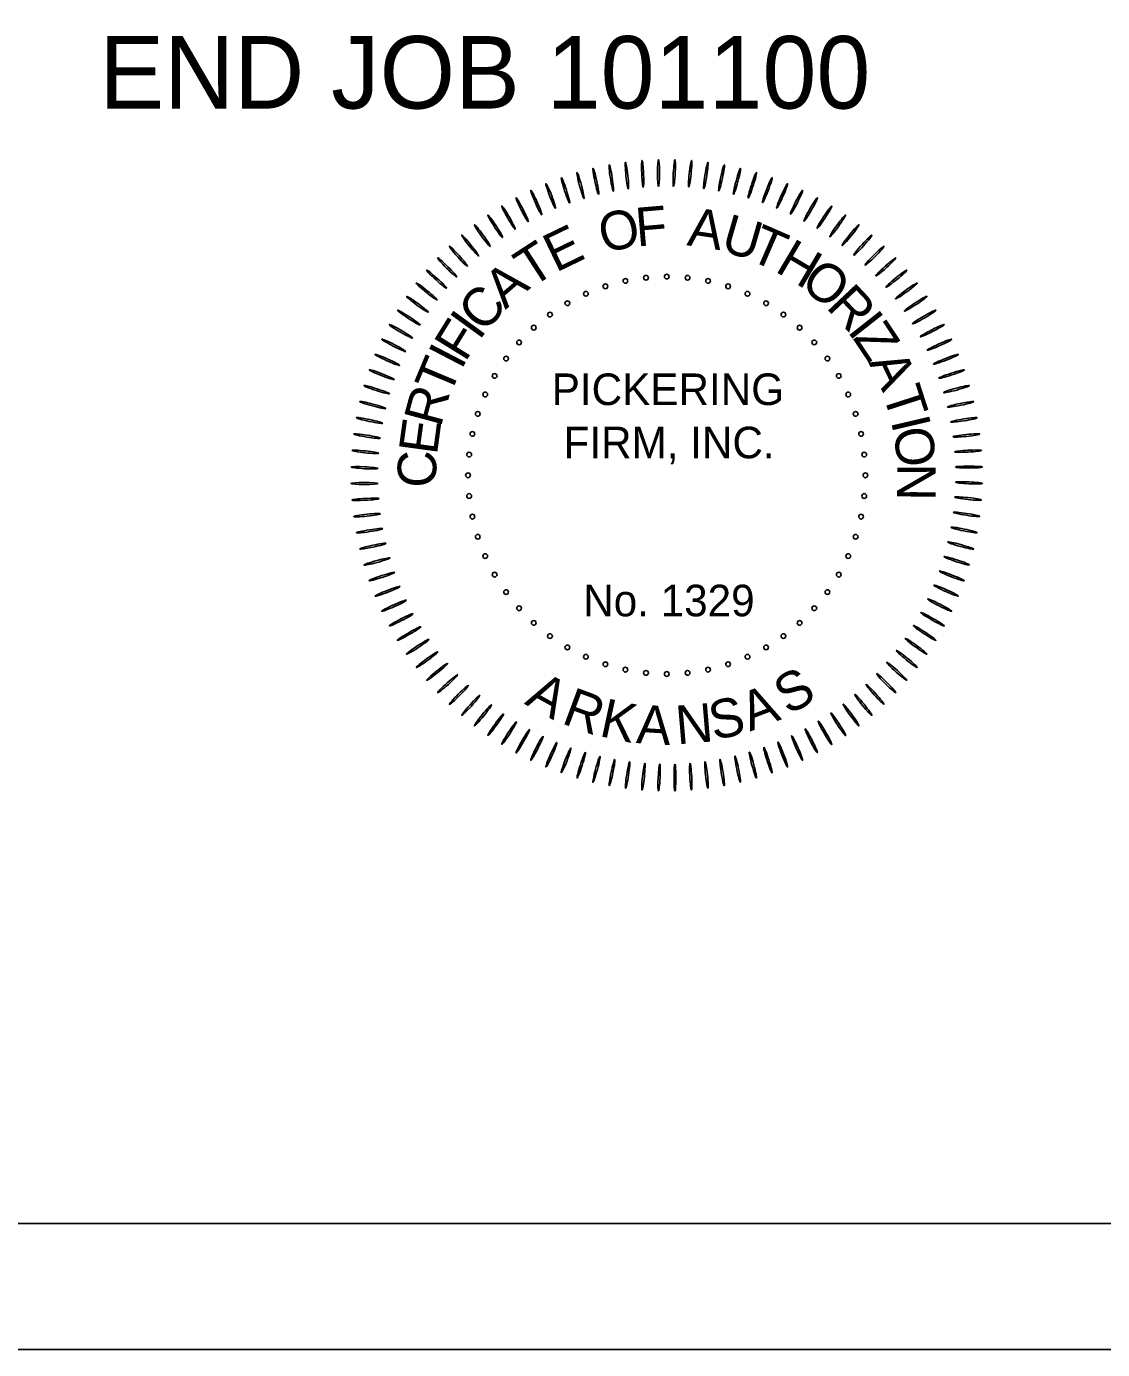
# Model space of a CAD drawing. Extents: x -0.3 to 2.65, y 0 to 1.9.
# Drawn here: x 1.0605 to 1.2386, y 0 to 0.2189 of the extents above; entities that cross this region are included whole.
import ezdxf

# ---------------------------------------------------------------- set-up
doc = ezdxf.new("R2010")
doc.units = 0
for name, color, linetype in [('Default', 7, 'Continuous'), ('Level 40', 7, 'Continuous'), ('Level 41', 7, 'Continuous'), ('Level 49', 7, 'Continuous'), ('SHET_Border-Lines', 7, 'Continuous')]:
    doc.layers.add(name, color=color, linetype=linetype)

# ---------------------------------------------------------------- blocks, each defined once
blk = doc.blocks.new('Pickering-COA AR-ENG_3')
at = {"layer": 'Level 40'}
for centre in [(-0.0427, 0.5137), (-0.0427, 0.5137), (-0.0228, 0.5168), (-0.0228, 0.5168), (-0.0028, 0.5179), (-0.0028, 0.5179), (0.0173, 0.5168), (0.0173, 0.5168), (0.0371, 0.5137), (0.0371, 0.5137), (-0.0808, 0.5013), (-0.0808, 0.5013), (-0.062, 0.5085), (-0.062, 0.5085), (0.0565, 0.5085), (0.0565, 0.5085), (0.0752, 0.5013), (0.0752, 0.5013), (-0.0987, 0.4922), (-0.0987, 0.4922), (0.0931, 0.4922), (0.0931, 0.4922), (-0.1155, 0.4812), (-0.1155, 0.4812), (0.1099, 0.4812), (0.1099, 0.4812), (-0.1311, 0.4686), (-0.1311, 0.4686), (0.1255, 0.4686), (0.1255, 0.4686), (-0.1453, 0.4544), (-0.1453, 0.4544), (0.1397, 0.4544), (0.1397, 0.4544), (-0.1579, 0.4388), (-0.1579, 0.4388), (0.1524, 0.4388), (0.1524, 0.4388), (-0.1689, 0.422), (-0.1689, 0.422), (0.1633, 0.422), (0.1633, 0.422), (-0.178, 0.4041), (-0.178, 0.4041), (0.1724, 0.4041), (0.1724, 0.4041), (-0.1852, 0.3854), (-0.1852, 0.3854), (0.1796, 0.3854), (0.1796, 0.3854), (-0.1904, 0.366), (-0.1904, 0.366), (0.1848, 0.366), (0.1848, 0.366), (-0.1935, 0.3461), (-0.1935, 0.3461), (0.1879, 0.3461), (0.1879, 0.3461), (-0.1946, 0.3261), (-0.1946, 0.3261), (0.189, 0.3261), (0.189, 0.3261), (-0.1935, 0.3061), (-0.1935, 0.3061), (0.1879, 0.3061), (0.1879, 0.3061), (-0.1904, 0.2862), (-0.1904, 0.2862), (0.1848, 0.2862), (0.1848, 0.2862), (-0.1852, 0.2668), (-0.1852, 0.2668), (0.1796, 0.2668), (0.1796, 0.2668), (-0.178, 0.2481), (-0.178, 0.2481), (0.1724, 0.2481), (0.1724, 0.2481), (-0.1689, 0.2302), (-0.1689, 0.2302), (0.1633, 0.2302), (0.1633, 0.2302), (-0.1579, 0.2134), (-0.1579, 0.2134), (0.1524, 0.2134), (0.1524, 0.2134), (-0.1453, 0.1978), (-0.1453, 0.1978), (0.1397, 0.1978), (0.1397, 0.1978), (-0.1311, 0.1836), (-0.1311, 0.1836), (0.1255, 0.1836), (0.1255, 0.1836), (-0.1155, 0.1709), (-0.1155, 0.1709), (0.1099, 0.1709), (0.1099, 0.1709), (-0.0987, 0.16), (-0.0987, 0.16), (0.0931, 0.16), (0.0931, 0.16), (-0.0808, 0.1509), (-0.0808, 0.1509), (-0.062, 0.1437), (-0.062, 0.1437), (-0.0427, 0.1385), (-0.0427, 0.1385), (0.0371, 0.1385), (0.0371, 0.1385), (0.0565, 0.1437), (0.0565, 0.1437), (0.0752, 0.1509), (0.0752, 0.1509), (-0.0228, 0.1354), (-0.0228, 0.1354), (-0.0028, 0.1343), (-0.0028, 0.1343), (0.0173, 0.1354), (0.0173, 0.1354)]:
    blk.add_circle(centre, 0.00229, dxfattribs=at)
for centre, major_axis in [((-0.0563, 0.613), (0.002, -0.0128)), ((-0.0563, 0.613), (0.002, -0.0128)), ((-0.0412, 0.6154), (0.0014, -0.0129)), ((-0.0412, 0.6154), (0.0014, -0.0129)), ((-0.026, 0.617), (0.0006, -0.013)), ((-0.026, 0.617), (0.0006, -0.013)), ((-0.0107, 0.6178), (0, -0.013)), ((-0.0107, 0.6178), (0, -0.013)), ((0.0045, 0.6178), (-0.0007, -0.013)), ((0.0045, 0.6178), (-0.0007, -0.013)), ((0.0198, 0.6171), (-0.0014, -0.0129)), ((0.0198, 0.6171), (-0.0014, -0.0129)), ((0.035, 0.6155), (-0.002, -0.0128)), ((0.035, 0.6155), (-0.002, -0.0128)), ((0.0501, 0.6131), (-0.0027, -0.0127)), ((0.0501, 0.6131), (-0.0027, -0.0127)), ((-0.1005, 0.6011), (0.004, -0.0124)), ((-0.1005, 0.6011), (0.004, -0.0124)), ((-0.086, 0.6058), (0.0034, -0.0126)), ((-0.086, 0.6058), (0.0034, -0.0126)), ((-0.0712, 0.6098), (0.0027, -0.0127)), ((-0.0712, 0.6098), (0.0027, -0.0127)), ((0.065, 0.6099), (-0.0034, -0.0126)), ((0.065, 0.6099), (-0.0034, -0.0126)), ((0.0798, 0.606), (-0.004, -0.0124)), ((0.0798, 0.606), (-0.004, -0.0124)), ((0.0943, 0.6013), (-0.0047, -0.0121)), ((0.0943, 0.6013), (-0.0047, -0.0121)), ((-0.1287, 0.5894), (0.0053, -0.0119)), ((-0.1287, 0.5894), (0.0053, -0.0119)), ((-0.1147, 0.5956), (0.0047, -0.0121)), ((-0.1147, 0.5956), (0.0047, -0.0121)), ((0.1086, 0.5958), (-0.0053, -0.0119)), ((0.1086, 0.5958), (-0.0053, -0.0119)), ((0.1225, 0.5896), (-0.0059, -0.0116)), ((0.1225, 0.5896), (-0.0059, -0.0116)), ((-0.1423, 0.5824), (0.0059, -0.0116)), ((-0.1423, 0.5824), (0.0059, -0.0116)), ((0.1362, 0.5827), (-0.0065, -0.0113)), ((0.1362, 0.5827), (-0.0065, -0.0113)), ((-0.1683, 0.5664), (0.0071, -0.0109)), ((-0.1683, 0.5664), (0.0071, -0.0109)), ((-0.1555, 0.5748), (0.0065, -0.0113)), ((-0.1555, 0.5748), (0.0065, -0.0113)), ((0.1494, 0.5751), (-0.0071, -0.0109)), ((0.1494, 0.5751), (-0.0071, -0.0109)), ((0.1622, 0.5668), (-0.0076, -0.0105)), ((0.1622, 0.5668), (-0.0076, -0.0105)), ((-0.1807, 0.5574), (0.0076, -0.0105)), ((-0.1807, 0.5574), (0.0076, -0.0105)), ((0.1746, 0.5578), (-0.0082, -0.0101)), ((0.1746, 0.5578), (-0.0082, -0.0101)), ((-0.1925, 0.5478), (0.0082, -0.0101)), ((-0.1925, 0.5478), (0.0082, -0.0101)), ((0.1865, 0.5482), (-0.0087, -0.00967)), ((0.1865, 0.5482), (-0.0087, -0.00967)), ((-0.2039, 0.5376), (0.0087, -0.00967)), ((-0.2039, 0.5376), (0.0087, -0.00967)), ((0.1978, 0.538), (-0.0092, -0.0092)), ((0.1978, 0.538), (-0.0092, -0.0092)), ((-0.2249, 0.5154), (0.00967, -0.0087)), ((-0.2249, 0.5154), (0.00967, -0.0087)), ((-0.2147, 0.5268), (0.0092, -0.0092)), ((-0.2147, 0.5268), (0.0092, -0.0092)), ((0.2087, 0.5272), (-0.00967, -0.0087)), ((0.2087, 0.5272), (-0.00967, -0.0087)), ((0.2189, 0.5159), (-0.0101, -0.0082)), ((0.2189, 0.5159), (-0.0101, -0.0082)), ((-0.2345, 0.5035), (0.0101, -0.0082)), ((-0.2345, 0.5035), (0.0101, -0.0082)), ((0.2285, 0.504), (-0.0105, -0.0076)), ((0.2285, 0.504), (-0.0105, -0.0076)), ((-0.2434, 0.4911), (0.0105, -0.0076)), ((-0.2434, 0.4911), (0.0105, -0.0076)), ((0.2375, 0.4917), (-0.0109, -0.0071)), ((0.2375, 0.4917), (-0.0109, -0.0071)), ((-0.2517, 0.4783), (0.0109, -0.0071)), ((-0.2517, 0.4783), (0.0109, -0.0071)), ((0.2458, 0.4789), (-0.0113, -0.0065)), ((0.2458, 0.4789), (-0.0113, -0.0065)), ((-0.2594, 0.4651), (0.0113, -0.0065)), ((-0.2594, 0.4651), (0.0113, -0.0065)), ((0.2535, 0.4657), (-0.0116, -0.0059)), ((0.2535, 0.4657), (-0.0116, -0.0059)), ((-0.2663, 0.4515), (0.0116, -0.0059)), ((-0.2663, 0.4515), (0.0116, -0.0059)), ((0.2604, 0.4521), (-0.0119, -0.0053)), ((0.2604, 0.4521), (-0.0119, -0.0053)), ((-0.2725, 0.4375), (0.0119, -0.0053)), ((-0.2725, 0.4375), (0.0119, -0.0053)), ((0.2667, 0.4381), (-0.0121, -0.0047)), ((0.2667, 0.4381), (-0.0121, -0.0047)), ((-0.2779, 0.4232), (0.0121, -0.0047)), ((-0.2779, 0.4232), (0.0121, -0.0047)), ((0.2722, 0.4238), (-0.0124, -0.004)), ((0.2722, 0.4238), (-0.0124, -0.004)), ((-0.2827, 0.4087), (0.0124, -0.004)), ((-0.2827, 0.4087), (0.0124, -0.004)), ((0.2769, 0.4093), (-0.0126, -0.0034)), ((0.2769, 0.4093), (-0.0126, -0.0034)), ((-0.2866, 0.3939), (0.0126, -0.0034)), ((-0.2866, 0.3939), (0.0126, -0.0034)), ((0.2809, 0.3946), (-0.0127, -0.0027)), ((0.2809, 0.3946), (-0.0127, -0.0027)), ((-0.2897, 0.379), (0.0127, -0.0027)), ((-0.2897, 0.379), (0.0127, -0.0027)), ((0.2841, 0.3796), (-0.0128, -0.002)), ((0.2841, 0.3796), (-0.0128, -0.002)), ((-0.2921, 0.3639), (0.0128, -0.002)), ((-0.2921, 0.3639), (0.0128, -0.002)), ((0.2865, 0.3646), (-0.0129, -0.0013)), ((0.2865, 0.3646), (-0.0129, -0.0013)), ((-0.2937, 0.3487), (0.0129, -0.0014)), ((-0.2937, 0.3487), (0.0129, -0.0014)), ((0.2881, 0.3494), (-0.013, -0.0007)), ((0.2881, 0.3494), (-0.013, -0.0007)), ((-0.2945, 0.3334), (0.013, -0.0007)), ((-0.2945, 0.3334), (0.013, -0.0007)), ((0.2889, 0.3341), (-0.013, 0)), ((0.2889, 0.3341), (-0.013, 0)), ((0.2889, 0.3188), (-0.013, 0.0006)), ((0.2889, 0.3188), (-0.013, 0.0006)), ((-0.2945, 0.3182), (0.013, 0)), ((-0.2945, 0.3182), (0.013, 0)), ((-0.2936, 0.3029), (0.013, 0.0007)), ((-0.2936, 0.3029), (0.013, 0.0007)), ((0.2881, 0.3036), (-0.0129, 0.0014)), ((0.2881, 0.3036), (-0.0129, 0.0014)), ((-0.292, 0.2876), (0.0129, 0.0013)), ((-0.292, 0.2876), (0.0129, 0.0013)), ((0.2866, 0.2884), (-0.0128, 0.002)), ((0.2866, 0.2884), (-0.0128, 0.002)), ((-0.2896, 0.2726), (0.0128, 0.002)), ((-0.2896, 0.2726), (0.0128, 0.002)), ((0.2842, 0.2733), (-0.0127, 0.0027)), ((0.2842, 0.2733), (-0.0127, 0.0027)), ((-0.2864, 0.2577), (0.0127, 0.0027)), ((-0.2864, 0.2577), (0.0127, 0.0027)), ((0.281, 0.2583), (-0.0126, 0.0034)), ((0.281, 0.2583), (-0.0126, 0.0034)), ((-0.2825, 0.2429), (0.0126, 0.0034)), ((-0.2825, 0.2429), (0.0126, 0.0034)), ((0.2771, 0.2436), (-0.0124, 0.004)), ((0.2771, 0.2436), (-0.0124, 0.004)), ((-0.2777, 0.2284), (0.0124, 0.004)), ((-0.2777, 0.2284), (0.0124, 0.004)), ((0.2724, 0.229), (-0.0121, 0.0047)), ((0.2724, 0.229), (-0.0121, 0.0047)), ((-0.2722, 0.2142), (0.0121, 0.0047)), ((-0.2722, 0.2142), (0.0121, 0.0047)), ((0.2669, 0.2148), (-0.0119, 0.0053)), ((0.2669, 0.2148), (-0.0119, 0.0053)), ((-0.266, 0.2002), (0.0119, 0.0053)), ((-0.266, 0.2002), (0.0119, 0.0053)), ((0.2607, 0.2008), (-0.0116, 0.0059)), ((0.2607, 0.2008), (-0.0116, 0.0059)), ((-0.2591, 0.1866), (0.0116, 0.0059)), ((-0.2591, 0.1866), (0.0116, 0.0059)), ((0.2538, 0.1872), (-0.0113, 0.0065)), ((0.2538, 0.1872), (-0.0113, 0.0065)), ((-0.2514, 0.1734), (0.0113, 0.0065)), ((-0.2514, 0.1734), (0.0113, 0.0065)), ((0.2462, 0.1739), (-0.0109, 0.0071)), ((0.2462, 0.1739), (-0.0109, 0.0071)), ((-0.2431, 0.1606), (0.0109, 0.0071)), ((-0.2431, 0.1606), (0.0109, 0.0071)), ((0.2379, 0.1611), (-0.0105, 0.0076)), ((0.2379, 0.1611), (-0.0105, 0.0076)), ((-0.2341, 0.1482), (0.0105, 0.0076)), ((-0.2341, 0.1482), (0.0105, 0.0076)), ((0.2289, 0.1488), (-0.0101, 0.0082)), ((0.2289, 0.1488), (-0.0101, 0.0082)), ((-0.2244, 0.1364), (0.0101, 0.0082)), ((-0.2244, 0.1364), (0.0101, 0.0082)), ((0.2193, 0.1369), (-0.00967, 0.0087)), ((0.2193, 0.1369), (-0.00967, 0.0087)), ((-0.2142, 0.125), (0.00967, 0.0087)), ((-0.2142, 0.125), (0.00967, 0.0087)), ((0.2091, 0.1255), (-0.0092, 0.0092)), ((0.2091, 0.1255), (-0.0092, 0.0092)), ((-0.2034, 0.1142), (0.0092, 0.0092)), ((-0.2034, 0.1142), (0.0092, 0.0092)), ((0.1983, 0.1147), (-0.0087, 0.00967)), ((0.1983, 0.1147), (-0.0087, 0.00967)), ((-0.192, 0.104), (0.0087, 0.00967)), ((-0.192, 0.104), (0.0087, 0.00967)), ((-0.1802, 0.0944), (0.0082, 0.0101)), ((-0.1802, 0.0944), (0.0082, 0.0101)), ((0.1751, 0.0948), (-0.0076, 0.0105)), ((0.1751, 0.0948), (-0.0076, 0.0105)), ((0.187, 0.1045), (-0.0082, 0.0101)), ((0.187, 0.1045), (-0.0082, 0.0101)), ((-0.1678, 0.0855), (0.0076, 0.0105)), ((-0.1678, 0.0855), (0.0076, 0.0105)), ((0.1628, 0.0858), (-0.0071, 0.0109)), ((0.1628, 0.0858), (-0.0071, 0.0109)), ((-0.155, 0.0772), (0.0071, 0.0109)), ((-0.155, 0.0772), (0.0071, 0.0109)), ((-0.1417, 0.0695), (0.0065, 0.0113)), ((-0.1417, 0.0695), (0.0065, 0.0113)), ((0.1367, 0.0699), (-0.0059, 0.0116)), ((0.1367, 0.0699), (-0.0059, 0.0116)), ((0.15, 0.0775), (-0.0065, 0.0113)), ((0.15, 0.0775), (-0.0065, 0.0113)), ((-0.1281, 0.0626), (0.0059, 0.0116)), ((-0.1281, 0.0626), (0.0059, 0.0116)), ((-0.1141, 0.0564), (0.0053, 0.0119)), ((-0.1141, 0.0564), (0.0053, 0.0119)), ((0.1092, 0.0567), (-0.0047, 0.0121)), ((0.1092, 0.0567), (-0.0047, 0.0121)), ((0.1231, 0.0629), (-0.0053, 0.0119)), ((0.1231, 0.0629), (-0.0053, 0.0119)), ((-0.0999, 0.051), (0.0047, 0.0121)), ((-0.0999, 0.051), (0.0047, 0.0121)), ((-0.0853, 0.0463), (0.004, 0.0124)), ((-0.0853, 0.0463), (0.004, 0.0124)), ((-0.0706, 0.0423), (0.0034, 0.0126)), ((-0.0706, 0.0423), (0.0034, 0.0126)), ((-0.0556, 0.0392), (0.0027, 0.0127)), ((-0.0556, 0.0392), (0.0027, 0.0127)), ((0.0507, 0.0393), (-0.002, 0.0128)), ((0.0507, 0.0393), (-0.002, 0.0128)), ((0.0657, 0.0425), (-0.0027, 0.0127)), ((0.0657, 0.0425), (-0.0027, 0.0127)), ((0.0804, 0.0464), (-0.0034, 0.0126)), ((0.0804, 0.0464), (-0.0034, 0.0126)), ((0.0949, 0.0512), (-0.004, 0.0124)), ((0.0949, 0.0512), (-0.004, 0.0124)), ((-0.0405, 0.0368), (0.002, 0.0128)), ((-0.0405, 0.0368), (0.002, 0.0128)), ((-0.0253, 0.0352), (0.0014, 0.0129)), ((-0.0253, 0.0352), (0.0014, 0.0129)), ((-0.0101, 0.0344), (0.0007, 0.013)), ((-0.0101, 0.0344), (0.0007, 0.013)), ((0.0052, 0.0344), (0, 0.013)), ((0.0052, 0.0344), (0, 0.013)), ((0.0204, 0.0353), (-0.0007, 0.013)), ((0.0204, 0.0353), (-0.0007, 0.013)), ((0.0356, 0.0369), (-0.0014, 0.0129)), ((0.0356, 0.0369), (-0.0014, 0.0129))]:
    blk.add_ellipse(centre, major_axis=major_axis, ratio=0.070301, dxfattribs=at)
at = {"layer": 'Level 41'}
for s, rotation, p in [('O', 12.2619, (-0.064, 0.5405)), ('F', 4.8299, (-0.0315, 0.5469)), ('A', 351.5891, (0.016, 0.5482)), ('U', 343.8069, (0.048, 0.543)), ('E', 25.8553, (-0.1098, 0.5215)), ('T', 336.5727, (0.0748, 0.5349)), ('T', 32.9353, (-0.1337, 0.5064)), ('H', 329.3464, (0.1006, 0.5235)), ('A', 40.7411, (-0.1586, 0.4856)), ('O', 321.4937, (0.1246, 0.5091)), ('C', 48.8967, (-0.1791, 0.4624)), ('R', 313.2703, (0.1502, 0.4882)), ('F', 58.2456, (-0.1973, 0.4346)), ('I', 53.972, (-0.1839, 0.4554)), ('I', 308.2054, (0.1708, 0.4653)), ('Z', 303.4877, (0.1763, 0.4587)), ('I', 62.5192, (-0.2011, 0.427)), ('T', 67.2448, (-0.2125, 0.4013)), ('A', 295.6897, (0.1917, 0.4351)), ('R', 74.8418, (-0.221, 0.3716)), ('T', 287.884, (0.2053, 0.4057)), ('E', 82.2613, (-0.2247, 0.345)), ('I', 283.1584, (0.2134, 0.3787)), ('O', 277.8065, (0.2157, 0.3704)), ('C', 89.6911, (-0.2253, 0.3141)), ('N', 269.9408, (0.2197, 0.3376)), ('A', 331.0076, (-0.1409, 0.1057)), ('S', 29.451, (0.1146, 0.0941)), ('R', 339.6665, (-0.1054, 0.0871)), ('A', 21.072, (0.0776, 0.0787)), ('K', 347.9673, (-0.069, 0.0746)), ('A', 356.4471, (-0.0328, 0.0677)), ('N', 4.7993, (0.0073, 0.0663)), ('S', 12.6929, (0.0427, 0.0701))]:
    blk.add_text(s, height=0.0373, rotation=rotation, dxfattribs=at).set_placement(p)
for s, p in [('PICKERING', (-0.1138, 0.3939)), ('FIRM, INC.', (-0.1024, 0.3425)), ('No. 1329', (-0.0834, 0.19))]:
    blk.add_text(s, height=0.03049, dxfattribs=at).set_placement(p)

msp = doc.modelspace()

# ---------------------------------------------------------------- linework, layer by layer
at = {"layer": 'SHET_Border-Lines'}
for points in [[(0, 0), (1.41667, 0), (1.41667, 0.91667), (0, 0.91667)], [(0.02083, 0.02083), (1.39583, 0.02083), (1.39583, 0.89583), (0.02083, 0.89583)]]:
    msp.add_lwpolyline(points, close=True, dxfattribs=at)

# ---------------------------------------------------------------- block references
at = {"layer": 'Level 49', "xscale": 0.17140689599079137, "yscale": 0.17140689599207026}
msp.add_blockref('Pickering-COA AR-ENG_3', (1.16697, 0.08875), dxfattribs=at)

# ---------------------------------------------------------------- texts
at = {"layer": 'Default'}
msp.add_text('END JOB 101100', height=0.012, dxfattribs=at).set_placement((1.07263, 0.20532))

doc.saveas('drawing.dxf')
